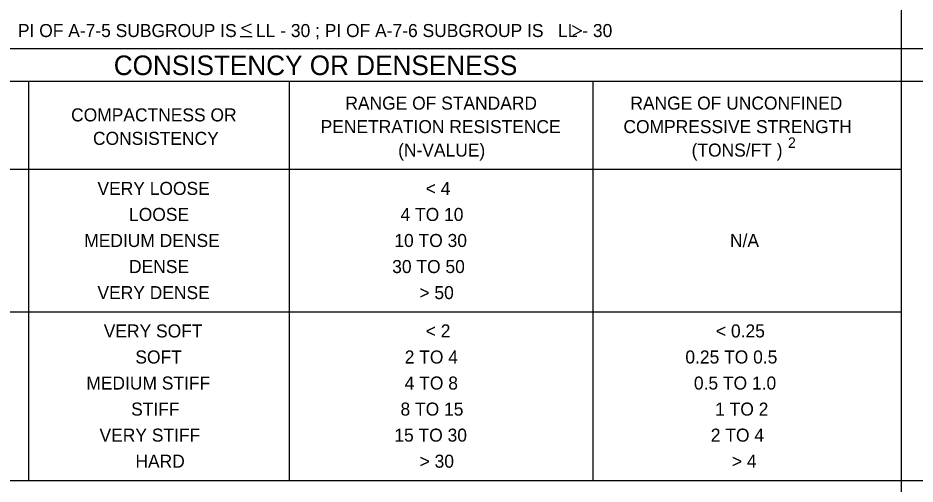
# Model space of a CAD drawing. Extents: x 278618 to 280654, y 171155 to 171855.
# Drawn here: x 280482.47 to 280512.35, y 171577.39 to 171592.9 of the extents above; entities that cross this region are included whole.
import ezdxf

# ---------------------------------------------------------------- set-up
doc = ezdxf.new("R2010")
doc.units = 0
doc.layers.add('Geotech Sheets and Borders Cell', color=7, linetype='Continuous')

msp = doc.modelspace()

# ---------------------------------------------------------------- linework, layer by layer
at = {"layer": 'Geotech Sheets and Borders Cell'}
for p, q in [((280511.888, 171621.702), (280511.888, 171541.488)), ((280489.878, 171592.276), (280490.277, 171592.276)), ((280549.148, 171591.865), (280474.148, 171591.865)), ((280549.148, 171590.781), (280474.148, 171590.781)), ((280482.824, 171590.781), (280482.824, 171577.514)), ((280491.5, 171590.781), (280491.5, 171577.514)), ((280501.614, 171590.781), (280501.614, 171577.514)), ((280474.148, 171587.864), (280511.888, 171587.864)), ((280474.148, 171583.122), (280511.888, 171583.122)), ((280474.148, 171577.514), (280549.148, 171577.514))]:
    msp.add_line(p, q, dxfattribs=at)
for points in [[(280490.236, 171592.687), (280489.92, 171592.557), (280490.236, 171592.401)], [(280500.933, 171592.651), (280501.245, 171592.469), (280500.954, 171592.313)]]:
    msp.add_lwpolyline(points, dxfattribs=at)

# ---------------------------------------------------------------- texts
for s, height, p in [('PI OF A-7-5 SUBGROUP IS    LL - 30 ; PI OF A-7-6 SUBGROUP IS   LL - 30', 0.43381, (280482.472, 171592.262)), ('CONSISTENCY OR DENSENESS', 0.6507, (280485.664, 171590.997)), ('RANGE OF STANDARD', 0.43381, (280493.377, 171589.847)), ('RANGE OF UNCONFINED', 0.43381, (280502.869, 171589.847)), ('COMPACTNESS OR', 0.43381, (280484.243, 171589.456)), ('PENETRATION RESISTENCE', 0.43381, (280492.553, 171589.066)), ('COMPRESSIVE STRENGTH', 0.43381, (280502.637, 171589.066)), ('CONSISTENCY', 0.43381, (280484.971, 171588.675)), ('2', 0.347, (280508.12, 171588.575)), ('(N-VALUE)', 0.4338, (280495.134, 171588.285)), ('(TONS/FT )', 0.4338, (280504.907, 171588.285)), ('VERY LOOSE', 0.4338, (280485.121, 171587.01)), ('< 4', 0.4338, (280496.053, 171587.01)), ('LOOSE', 0.4338, (280486.173, 171586.143)), ('4 TO 10', 0.4338, (280495.213, 171586.143)), ('MEDIUM DENSE', 0.43381, (280484.681, 171585.277)), ('10 TO 30', 0.4338, (280495.008, 171585.277)), ('N/A', 0.4338, (280506.186, 171585.277)), ('DENSE', 0.4338, (280486.173, 171584.41)), ('30 TO 50', 0.4338, (280494.937, 171584.41)), ('VERY DENSE', 0.4338, (280485.121, 171583.543)), ('> 50', 0.4338, (280495.842, 171583.543)), ('VERY SOFT', 0.4338, (280485.331, 171582.268)), ('< 2', 0.4338, (280496.053, 171582.268)), ('< 0.25', 0.4338, (280505.718, 171582.268)), ('SOFT', 0.4338, (280486.383, 171581.401)), ('2 TO 4', 0.4338, (280495.353, 171581.401)), ('0.25 TO 0.5', 0.43381, (280504.7, 171581.401)), ('MEDIUM STIFF', 0.43381, (280484.749, 171580.534)), ('4 TO 8', 0.4338, (280495.353, 171580.534)), ('0.5 TO 1.0', 0.4338, (280504.984, 171580.534)), ('STIFF', 0.4338, (280486.242, 171579.668)), ('8 TO 15', 0.4338, (280495.213, 171579.668)), ('1 TO 2', 0.4338, (280505.691, 171579.668)), ('VERY STIFF', 0.4338, (280485.19, 171578.801)), ('15 TO 30', 0.4338, (280495.008, 171578.801)), ('2 TO 4', 0.4338, (280505.547, 171578.801)), ('HARD', 0.4338, (280486.385, 171577.934)), ('> 30', 0.4338, (280495.849, 171577.934)), ('> 4', 0.4338, (280506.248, 171577.934))]:
    msp.add_text(s, height=height, dxfattribs=at).set_placement(p)

doc.saveas('drawing.dxf')
